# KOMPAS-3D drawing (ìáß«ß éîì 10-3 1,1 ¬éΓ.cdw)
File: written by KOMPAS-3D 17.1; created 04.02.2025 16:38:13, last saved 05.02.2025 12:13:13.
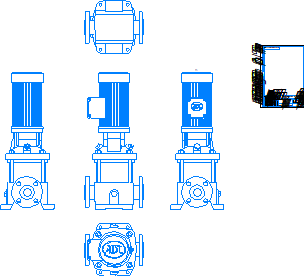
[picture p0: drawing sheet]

Sheet 1: A4, portrait

Title block, sheet 1: name: Насос ВМН 10-3 1,1 / кВт; designation: Насос ВМН 10-3 1,1 кВт; material: Сталь 10  ГОСТ 1050-2013; mass: 112,48; sheets: 1; sheet format: A4; stored path: \\adlc.lan\data\АДЛ_ПКД\3D-модели\ADL production\Насосы ГРАНПАМП\Насосы ВМН\ВМН10\KOMPAS 3D\Насос ВМН 10-3 1,1 кВт.cdw

Views: Проекционный вид 2, Проекционный вид 3, Проекционный вид 4, Проекционный вид 5
Referenced files in \\adlc.lan\data\АДЛ_ПКД\3D-модели\ADL production\Насосы ГРАНПАМП\Насосы ВМН\ВМН10\KOMPAS 3D\: ВМН 10-3 1,1 кВт.m3d, Насос ВМН 10-3 1,1 кВт.m3d
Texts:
  Andrey
  АДЛ
Dimensions and other numbers on the sheet: 1:1; 1; 112,48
